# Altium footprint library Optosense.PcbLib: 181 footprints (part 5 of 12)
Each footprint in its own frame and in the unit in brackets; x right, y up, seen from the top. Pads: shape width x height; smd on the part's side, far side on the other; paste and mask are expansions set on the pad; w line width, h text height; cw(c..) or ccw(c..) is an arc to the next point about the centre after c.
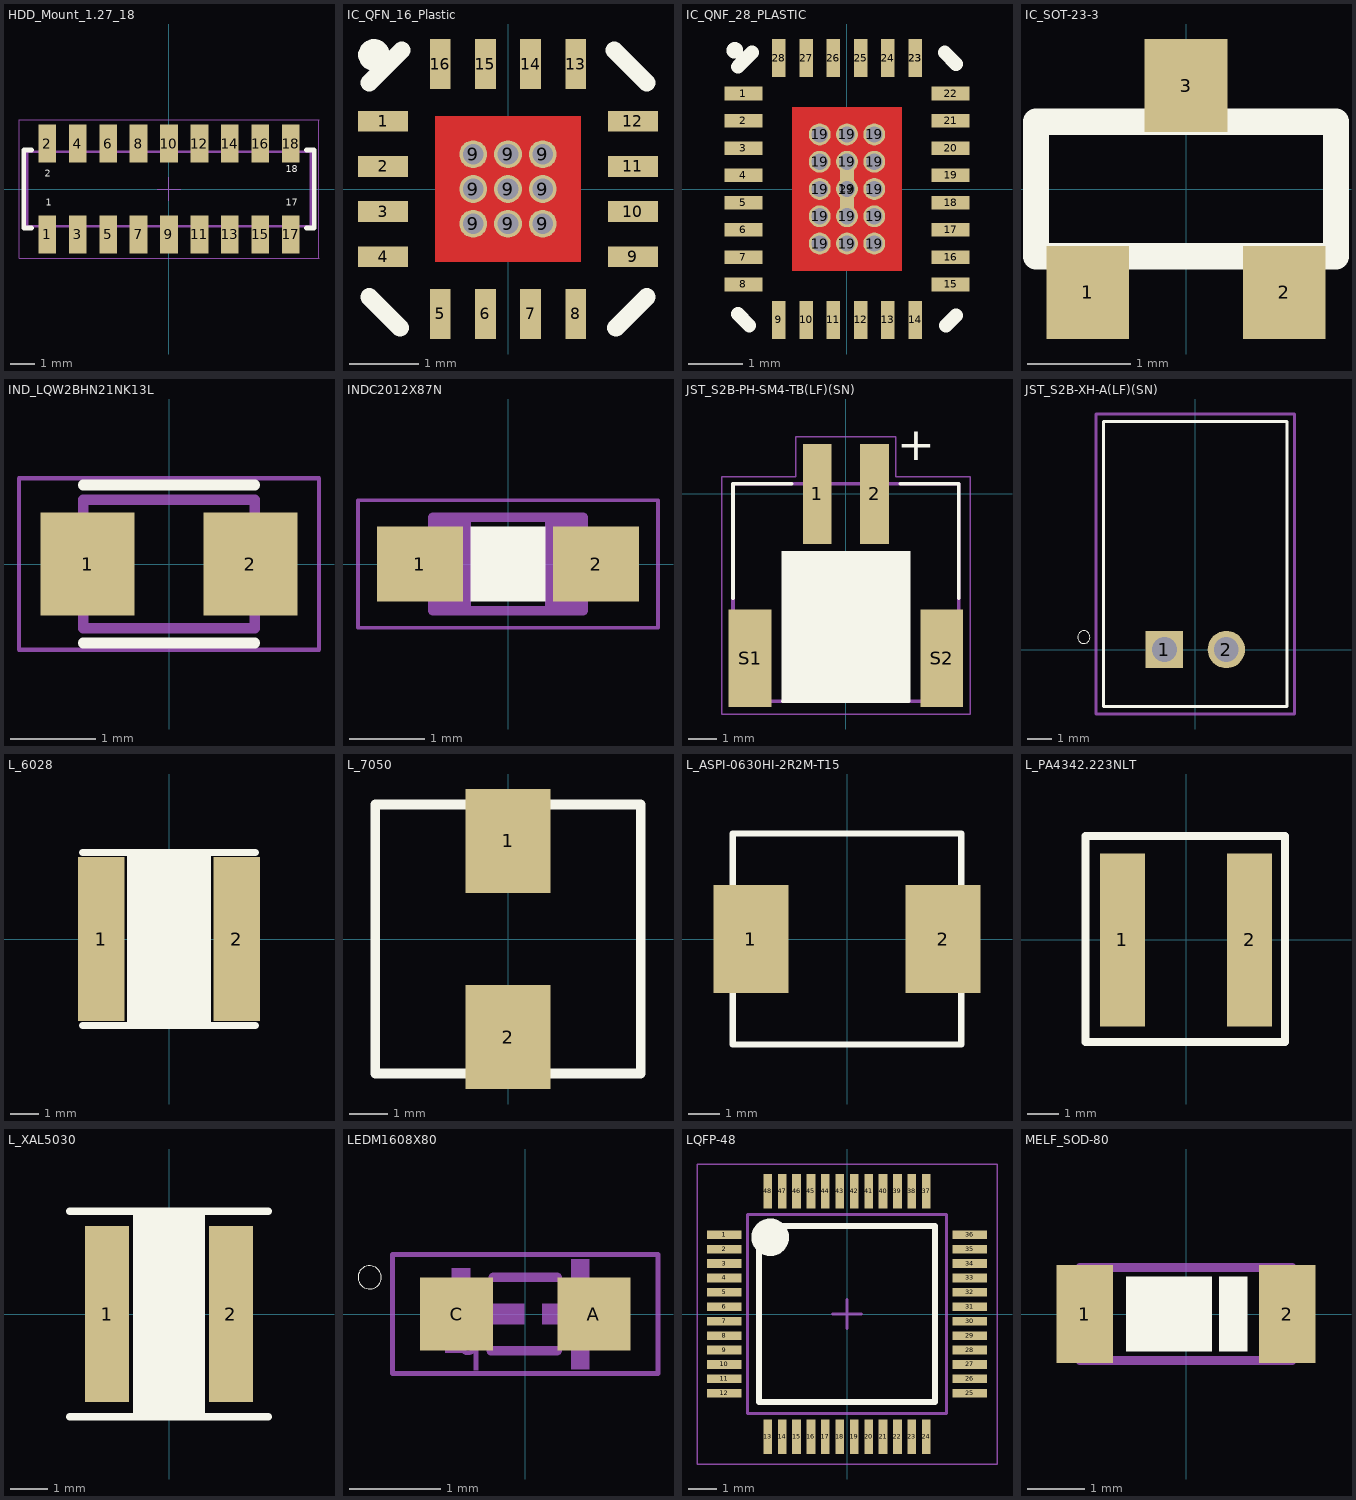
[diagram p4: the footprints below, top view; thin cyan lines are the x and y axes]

## HDD_Mount_1.27_18 [mm] "Socket Header, Pitch 1.27 mm, SMT, Vertical, dual row, 26p"
height 2.35
pads (18):
  rect 0.74x1.6 smd: 1(-5.08,-1.9) 2(-5.08,1.9) 3(-3.81,-1.9) 4(-3.81,1.9) 5(-2.54,-1.9) 6(-2.54,1.9) 7(-1.27,-1.9) 8(-1.27,1.9) 9(0,-1.9) 10(0,1.9) 11(1.27,-1.9) 12(1.27,1.9) 13(2.54,-1.9) 14(2.54,1.9) 15(3.81,-1.9) 16(3.81,1.9) 17(5.08,-1.9) 18(5.08,1.9)
Top Overlay:
  lines w0.2: -5.74,-1.625 -6.065,-1.625 -6.065,1.625 -5.74,1.625 ; 5.74,-1.625 6.065,-1.625 6.065,1.625 5.74,1.625
  text "17" at 4.867,-0.8 h0.5
  text "18" at 4.866,0.6 h0.5
  text "2" at -5.186,0.4 h0.5
  text "1" at -5.139,-0.8 h0.5
Top 3D Body:
  lines w0.1: -5.28,-1.55 -5.28,-2.2 -4.88,-2.2 -4.88,-1.55 ; -5.28,1.55 -5.28,2.2 -4.88,2.2 -4.88,1.55 ; -4.01,-1.55 -4.01,-2.2 -3.61,-2.2 -3.61,-1.55 ; -4.01,1.55 -4.01,2.2 -3.61,2.2 -3.61,1.55 ; -2.74,-1.55 -2.74,-2.2 -2.34,-2.2 -2.34,-1.55 ; -2.74,1.55 -2.74,2.2 -2.34,2.2 -2.34,1.55 ; -1.47,-1.55 -1.47,-2.2 -1.07,-2.2 -1.07,-1.55 ; -1.47,1.55 -1.47,2.2 -1.07,2.2 -1.07,1.55 ; -0.2,-1.55 -0.2,-2.2 0.2,-2.2 0.2,-1.55 ; -0.2,1.55 -0.2,2.2 0.2,2.2 0.2,1.55 ; 1.07,-1.55 1.07,-2.2 1.47,-2.2 1.47,-1.55 ; 1.07,1.55 1.07,2.2 1.47,2.2 1.47,1.55 ; 2.34,-1.55 2.34,-2.2 2.74,-2.2 2.74,-1.55 ; 2.34,1.55 2.34,2.2 2.74,2.2 2.74,1.55 ; 3.61,-1.55 3.61,-2.2 4.01,-2.2 4.01,-1.55 ; 3.61,1.55 3.61,2.2 4.01,2.2 4.01,1.55 ; 4.88,-1.55 4.88,-2.2 5.28,-2.2 5.28,-1.55 ; 4.88,1.55 4.88,2.2 5.28,2.2 5.28,1.55 ; -5.915,-1.55 -5.915,1.55 5.915,1.55 5.915,-1.55 -5.915,-1.55
Top Courtyard:
  lines w0.05: -0.5,0 0.5,0 ; 0,-0.5 0,0.5 ; -6.265,-2.9 6.265,-2.9 6.265,2.9 -6.265,2.9 -6.265,-2.9
Top Assembly:
  lines w0.1: -5.28,-1.55 -5.28,-2.2 -4.88,-2.2 -4.88,-1.55 ; -5.28,1.55 -5.28,2.2 -4.88,2.2 -4.88,1.55 ; -4.01,-1.55 -4.01,-2.2 -3.61,-2.2 -3.61,-1.55 ; -4.01,1.55 -4.01,2.2 -3.61,2.2 -3.61,1.55 ; -2.74,-1.55 -2.74,-2.2 -2.34,-2.2 -2.34,-1.55 ; -2.74,1.55 -2.74,2.2 -2.34,2.2 -2.34,1.55 ; -1.47,-1.55 -1.47,-2.2 -1.07,-2.2 -1.07,-1.55 ; -1.47,1.55 -1.47,2.2 -1.07,2.2 -1.07,1.55 ; -0.2,-1.55 -0.2,-2.2 0.2,-2.2 0.2,-1.55 ; -0.2,1.55 -0.2,2.2 0.2,2.2 0.2,1.55 ; 1.07,-1.55 1.07,-2.2 1.47,-2.2 1.47,-1.55 ; 1.07,1.55 1.07,2.2 1.47,2.2 1.47,1.55 ; 2.34,-1.55 2.34,-2.2 2.74,-2.2 2.74,-1.55 ; 2.34,1.55 2.34,2.2 2.74,2.2 2.74,1.55 ; 3.61,-1.55 3.61,-2.2 4.01,-2.2 4.01,-1.55 ; 3.61,1.55 3.61,2.2 4.01,2.2 4.01,1.55 ; 4.88,-1.55 4.88,-2.2 5.28,-2.2 5.28,-1.55 ; 4.88,1.55 4.88,2.2 5.28,2.2 5.28,1.55 ; -5.915,-1.55 -5.915,1.55 5.915,1.55 5.915,-1.55 -5.915,-1.55
3D body "HDD_Mount_1.27_18.step": height 2.1, standoff 0, extent -5.915,-2.2 5.915,2.2

## IC_QFN_16_Plastic [mm]
height 0.75
pads (25):
  rect 0.72x0.3 smd: 1(-1.8,0.975) 2(-1.8,0.325) 3(-1.8,-0.325) 4(-1.8,-0.975) 9(1.8,-0.975) 10(1.8,-0.325) 11(1.8,0.325) 12(1.8,0.975)
  rect 0.3x0.72 smd: 5(-0.975,-1.8) 6(-0.325,-1.8) 7(0.325,-1.8) 8(0.975,-1.8) 13(0.975,1.8) 14(0.325,1.8) 15(-0.325,1.8) 16(-0.975,1.8)
  round 0.4 hole 0.3: 9(-0.5,-0.5) 9(-0.5,0) 9(-0.5,0.5) 9(0,-0.5) 9(0,0) 9(0,0.5) 9(0.5,-0.5) 9(0.5,0) 9(0.5,0.5)
Top Layer:
  region: -1.05,-1.05 -1.05,1.05 1.05,1.05 1.05,-1.05
Top Overlay:
  circle w0.254: c-1.93,1.93 r0.1
  lines w0.254: -2,-1.556 -1.556,-2 ; -2,1.531 -1.531,2 ; 1.531,2 2,1.531 ; 1.556,-2 2,-1.556
3D body "ALSRobot-QFN16 4x4.STEP": height 0.92, standoff 0, extent -2,-2 2,2

## IC_QNF_28_PLASTIC [mm]
height 0.75
pads (45):
  rect 0.7x0.25 smd: 1(-1.9,1.75) 2(-1.9,1.25) 3(-1.9,0.75) 4(-1.9,0.25) 5(-1.9,-0.25) 6(-1.9,-0.75) 7(-1.9,-1.25) 8(-1.9,-1.75) 15(1.9,-1.75) 16(1.9,-1.25) 17(1.9,-0.75) 18(1.9,-0.25) 19(1.9,0.25) 20(1.9,0.75) 21(1.9,1.25) 22(1.9,1.75)
  rect 0.25x0.7 smd: 9(-1.25,-2.4) 10(-0.75,-2.4) 11(-0.25,-2.4) 12(0.25,-2.4) 13(0.75,-2.4) 14(1.25,-2.4) 23(1.25,2.4) 23(1.25,2.4) 24(0.75,2.4) 25(0.25,2.4) 26(-0.25,2.4) 27(-0.75,2.4) 28(-1.25,2.4)
  round 0.4 hole 0.3: 19(-0.5,-1) 19(-0.5,-0.5) 19(-0.5,0) 19(-0.5,0.5) 19(-0.5,1) 19(0,-1) 19(0,-0.5) 19(0,0) 19(0,0.5) 19(0,1) 19(0.5,-1) 19(0.5,-0.5) 19(0.5,0) 19(0.5,0.5) 19(0.5,1)
  rect 0.25x0.7 smd paste+0 mask+0: 29(0,0)
Top Layer:
  region: -1,1.5 -1,-1.5 1,-1.5 1,1.5
Top Overlay:
  circle w0.254: c-2.057,2.54 r0.025
  lines w0.254: -2,-2.293 -1.793,-2.5 ; -2,2.242 -1.742,2.5 ; 1.793,2.5 2,2.293 ; 1.818,-2.5 2,-2.318
3D body "User Library-QFN 28.STEP": height 0.7, standoff -0.05, extent -2.007,-2.495 2.003,2.515

## IC_SOT-23-3 [mm]
height 1.025
pads (3):
  rect 0.8x0.9 smd: 1(-0.95,-1) 2(0.95,-1) 3(0,1)
Top Overlay:
  lines w0.254: -1.45,-0.65 1.45,-0.65 1.45,0.65 -1.45,0.65 -1.45,-0.65

## IND_LQW2BHN21NK13L [mm]
pads (2):
  rect 1.1x1.2 smd: 1(-0.95,0) 2(0.95,0)
Top Overlay:
  lines w0.127: -1,-0.92 1,-0.92 ; -1,0.92 1,0.92
Mechanical 13:
  lines w0.127: -1,-0.75 -1,0.75 1,0.75 1,-0.75 -1,-0.75
Mechanical 15:
  lines w0.05: -1.75,-1 -1.75,1 1.75,1 1.75,-1 -1.75,-1

## INDC2012X87N [mm]
pads (2):
  rect 1.15x1 smd: 1(-1.175,0) 2(1.175,0)
Top Overlay:
  rectangle: -0.5,-0.5 0.5,0.5
Mechanical 13:
  region: -0.5,-0.625 -1,-0.625 -1,0.625 -0.5,0.625
  region: 1,-0.625 0.5,-0.625 0.5,0.625 1,0.625
  lines w0.127: -1,-0.625 1,-0.625 1,0.625 -1,0.625 -1,-0.625
Mechanical 15:
  lines w0.051: -2,-0.85 2,-0.85 2,0.85 -2,0.85 -2,-0.85
3D body: height 0.55, standoff 0.05, extent -1.6,-0.4 1.6,0.4

## JST_S2B-PH-SM4-TB(LF)(SN) [mm]
pads (4):
  rect 1x3.5 smd: 1(-1,0) 2(1,0)
  rect 1.5x3.4 smd: S1(-3.35,-5.75) S2(3.35,-5.75)
Top Overlay:
  rectangle: -2.25,-7.25 2.25,-2
  lines w0.127: -3.95,-3.65 -3.95,0.35 -1.9,0.35 ; -2.2,-7.25 2.2,-7.25 ; 1.9,0.35 3.95,0.35 3.95,-3.65
  text "+" at 3.125,0.793 h2
Mechanical 13:
  lines w0.127: -3.95,-7.25 -3.95,0.35 3.95,0.35 3.95,-7.25 -3.95,-7.25
Mechanical 15:
  lines w0.05: -4.35,-7.7 -4.35,0.6 -1.75,0.6 -1.75,2 1.75,2 1.75,0.6 4.35,0.6 4.35,-7.7 -4.35,-7.7
3D body "S2B-PH-SM4-TB(LF)(SN)--3DModel-STEP-56544.STEP": height 5.5, standoff -0.1, extent -3.95,-7.237 3.95,1.363

## JST_S2B-XH-A(LF)(SN) [mm]
pads (2):
  rect 1.508x1.508 hole 1: 1(-1.25,0)
  round 1.508 hole 1: 2(1.25,0)
Top Overlay:
  circle w0: c-4.5,0.5 r0.254
  lines w0.127: -3.7,-2.3 3.7,-2.3 3.7,9.2 -3.7,9.2 -3.7,-2.3
Mechanical 15:
  lines w0.127: -4,-2.6 4,-2.6 4,9.5 -4,9.5 -4,-2.6
3D body "step_temp.STEP": height 6.1, standoff -3.4, extent -3.7,-2.3 3.7,9.2

## L_6028 [mm] "NRS6028T101MMGJ"
height 2.8
pads (2):
  rect 1.6x5.7 smd: 1(-2.35,0) 2(2.35,0)
Top Overlay:
  rectangle: -1.448,-3 1.448,3
  lines w0.254: -3,-3 3,-3 ; -3,3 3,3
3D body "User Library-DJNR6028.STEP": height 2.58, standoff 0, extent -3.025,-3.047 2.975,3.098

## L_7050 [mm]
height 4.8
pads (2):
  rect 2.2x2.7 smd: 1(0,2.55) 2(0,-2.55)
Top Overlay:
  lines w0.254: -3.45,-3.5 -3.45,3.5 3.45,3.5 3.45,-3.5 -3.45,-3.5

## L_ASPI-0630HI-2R2M-T15 [mm] "ASPI-0630HI-2R2M-T15"
pads (2):
  rect 2.35x3.4 smd paste-0.2: 1(-3.025,0) 2(3.025,0)
Top Overlay:
  lines w0.2: -3.6,-3.325 -3.6,3.325 ; -3.6,-3.325 -3.6,3.325 ; -3.6,-3.325 3.6,-3.325 3.6,3.325 -3.6,3.325
Mechanical 15:
  lines w0.1: -3.6,-3.3 3.6,-3.3 3.6,3.3 -3.6,3.3 -3.6,-3.3
3D body "ASPI-0630HI.STEP": height 2.95, standoff -0.05, extent -3.6,-3.325 3.6,3.325

## L_PA4342.223NLT [mm]
pads (2):
  rect 1.43x5.5 smd: 1(-2.02,0) 2(2.02,0)
Top Overlay:
  lines w0.254: -3.2,-3.25 3.15,-3.25 3.15,3.3 -3.2,3.3 -3.2,-3.25

## L_XAL5030 [mil]
pads (2):
  rect 46x185 smd: 1(-65,0) 2(65,0)
Top Overlay:
  rectangle: -38,-108 38,108
  lines w7.87: -104,-108 104,-108 ; -104,108 104,108
3D body "Coilcraft-XAL5030.STEP": height 118.11, standoff -3.94, extent -107.88,-111.81 107.88,111.81

## LEDM1608X80 [mm]
pads (2):
  rect 0.8x0.8 smd: A(0.75,0) C(-0.75,0)
Top Overlay:
  circle w0: c-1.7,0.4 r0.127
Mechanical 13:
  circle w0.051: c-0.625,-0.35 r0.075
  region: -0.675,-0.425 -0.876,-0.425 -0.876,-0.275 -0.675,-0.275
  region: -0.55,-0.275 -0.601,-0.275 -0.601,-0.225 -0.55,-0.225
  region: -0.513,-0.613 -0.563,-0.613 -0.563,-0.238 -0.513,-0.238
  region: -0.6,0.2 -0.801,0.2 -0.801,0.5 -0.6,0.5
  region: -0.012,-0.113 -0.914,-0.113 -0.914,0.112 -0.012,0.112
  region: 0.7,-0.601 0.501,-0.601 0.501,-0.1 0.7,-0.1
  region: 0.7,0.1 0.501,0.1 0.501,0.6 0.7,0.6
  region: 0.737,-0.113 0.188,-0.113 0.188,0.112 0.737,0.112
  region: 0.65,-0.275 0.551,-0.275 0.551,-0.175 0.65,-0.175
  region: 0.65,0.175 0.551,0.175 0.551,0.275 0.65,0.275
  lines w0.051: 0.825,-0.275 cw(c0.825,0) 0.825,0.275
  lines w0.102: -0.8,-0.3 ccw(c-0.826,0) -0.8,0.3 ; -0.375,-0.4 0.35,-0.4 ; -0.35,0.4 0.35,0.4
Mechanical 15:
  lines w0.05: -1.45,-0.65 1.45,-0.65 1.45,0.65 -1.45,0.65 -1.45,-0.65
3D body "LTST-C190GKT.STEP": height 1.15, standoff 0, extent -0.8,-0.3 0.8,0.3

## LQFP-48 [mm] "LQFP-48, 48-Leads, Body 6,90x6,90mm, Pitch 0,50mm, IPC Medium Density"
height 1.6
pads (48):
  rect 1.2x0.3 smd paste-0.1: 1(-4.25,2.75) 2(-4.25,2.25) 3(-4.25,1.75) 4(-4.25,1.25) 5(-4.25,0.75) 6(-4.25,0.25) 7(-4.25,-0.25) 8(-4.25,-0.75) 9(-4.25,-1.25) 10(-4.25,-1.75) 11(-4.25,-2.25) 12(-4.25,-2.75) 25(4.25,-2.75) 26(4.25,-2.25) 27(4.25,-1.75) 28(4.25,-1.25) 29(4.25,-0.75) 30(4.25,-0.25) 31(4.25,0.25) 32(4.25,0.75) 33(4.25,1.25) 34(4.25,1.75) 35(4.25,2.25) 36(4.25,2.75)
  rect 0.3x1.2 smd paste-0.1: 13(-2.75,-4.25) 14(-2.25,-4.25) 15(-1.75,-4.25) 16(-1.25,-4.25) 17(-0.75,-4.25) 18(-0.25,-4.25) 19(0.25,-4.25) 20(0.75,-4.25) 21(1.25,-4.25) 22(1.75,-4.25) 23(2.25,-4.25) 24(2.75,-4.25) 37(2.75,4.25) 38(2.25,4.25) 39(1.75,4.25) 40(1.25,4.25) 41(0.75,4.25) 42(0.25,4.25) 43(-0.25,4.25) 44(-0.75,4.25) 45(-1.25,4.25) 46(-1.75,4.25) 47(-2.25,4.25) 48(-2.75,4.25)
Top Overlay:
  circle w0.7: c-2.663,2.659 r0.3
  lines w0.2: -3.05,-3.05 -3.05,3.05 3.05,3.05 3.05,-3.05 -3.05,-3.05
Mechanical 13:
  lines w0.1: -3.45,-3.45 -3.45,3.45 3.45,3.45 3.45,-3.45 -3.45,-3.45
Mechanical 15:
  lines w0.05: -5.2,-5.2 -5.2,5.2 5.2,5.2 5.2,-5.2 -5.2,-5.2
  lines w0.1: -0.5,0 0.5,0 ; 0,-0.5 0,0.5
3D body "LQFP-48.step": height 1.6, standoff 0, extent -4.5,-4.5 4.5,4.5

## MELF_SOD-80 [mil]
pads (2):
  rect 39x67 smd: 1(-69.5,0) 2(69.5,0)
Top Overlay:
  rectangle: -41.34,-25.59 17.72,25.59
  rectangle: 22.64,-25.59 42.32,25.59
Mechanical 13:
  lines w6: -73,-32 73,-32 73,32 -73,32 -73,-32
3D body "SOD-80 QuadroMELF.stp": height 62.99, standoff 0, extent -72.84,-31.49 72.83,31.5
